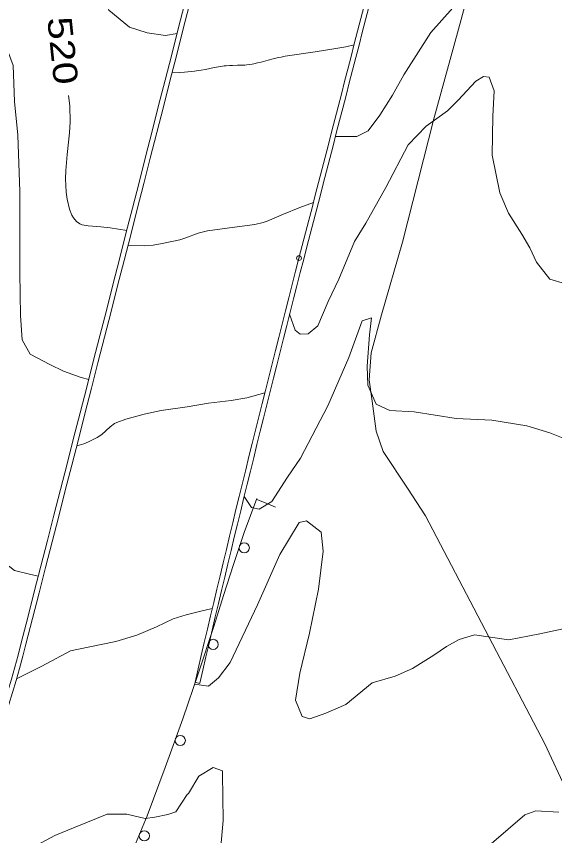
# Model space of a CAD drawing. Extents: x 2361284 to 2366480, y 6976556 to 6985346.
# Drawn here: x 2364928.4 to 2365034.3, y 6979218.9 to 6979380.2 of the extents above; entities that cross this region are included whole.
import ezdxf
from ezdxf.enums import TextEntityAlignment as Align

# ---------------------------------------------------------------- set-up
doc = ezdxf.new("R2010")
doc.units = 0
doc.header["$LTSCALE"] = 1.9
doc.header["$PDMODE"] = 32
doc.header["$PDSIZE"] = 0.95
for name, color, linetype, lineweight in [('12', 7, 'Continuous', 13), ('13', 7, 'Continuous', 13), ('17', 7, 'Continuous', 13), ('3', 7, 'Continuous', 13), ('5', 7, 'Continuous', 13)]:
    doc.layers.add(name, color=color, linetype=linetype, lineweight=lineweight)

msp = doc.modelspace()

# ---------------------------------------------------------------- linework, layer by layer
at = {"layer": '12'}
for points in [[(2365090.866, 6979426.919), (2365090.797, 6979426.888), (2365083.489, 6979425.51), (2365077.442, 6979424.101), (2365067.089, 6979423.363), (2365058.669, 6979422.293), (2365053.493, 6979419.673), (2365048.99, 6979416.8), (2365044.078, 6979409.723), (2365038.145, 6979403.617), (2365033.068, 6979398.048), (2365027.257, 6979391.763), (2365022.139, 6979387.334), (2365014.301, 6979381.889), (2365009.957, 6979377.046), (2365004.624, 6979368.746), (2365002.393, 6979364.705), (2364999.96, 6979360.762), (2364997.599, 6979357.698), (2364995.39, 6979356.567), (2364991.199, 6979356.597)], [(2364994.848, 6979374.593), (2364993.247, 6979374.248), (2364992.444, 6979374.089), (2364991.235, 6979373.878), (2364987.222, 6979373.26), (2364981.299, 6979372.364), (2364980.511, 6979372.226), (2364979.988, 6979372.116), (2364978.949, 6979371.868), (2364977.914, 6979371.596), (2364976.535, 6979371.232), (2364975.843, 6979371.062), (2364975.148, 6979370.908), (2364974.8, 6979370.839), (2364974.274, 6979370.747), (2364973.727, 6979370.675), (2364973.36, 6979370.643), (2364972.623, 6979370.604), (2364971.885, 6979370.588), (2364970.899, 6979370.571), (2364970.407, 6979370.553), (2364969.672, 6979370.502), (2364969.307, 6979370.46), (2364968.652, 6979370.365), (2364967.347, 6979370.135), (2364965.609, 6979369.798), (2364964.739, 6979369.64), (2364963.864, 6979369.503), (2364963.425, 6979369.445), (2364962.121, 6979369.302), (2364961.469, 6979369.242), (2364960.49, 6979369.168), (2364959.019, 6979369.093)], [(2364950.114, 6979338.077), (2364946.849, 6979338.586), (2364945.006, 6979338.78), (2364942.54, 6979338.992), (2364941.311, 6979339.203), (2364940.899, 6979339.34), (2364940.183, 6979339.829), (2364939.605, 6979340.531), (2364939.292, 6979341.075), (2364938.833, 6979342.229), (2364938.349, 6979344.235), (2364938.159, 6979345.573), (2364938.035, 6979348.261), (2364938.087, 6979349.856), (2364938.362, 6979353.047), (2364938.809, 6979357.303), (2364938.941, 6979359.428), (2364938.869, 6979362.611), (2364938.61, 6979364.638)]]:
    msp.add_lwpolyline(points, dxfattribs=at)
at = {"layer": '13'}
for points in [[(2364960.006, 6979376.831), (2364957.759, 6979376.44), (2364954.094, 6979376.955), (2364950.663, 6979378.123), (2364946.581, 6979381.425), (2364944.782, 6979386.648), (2364943.416, 6979393.555), (2364943.388, 6979402.775), (2364943.212, 6979412.914), (2364941.511, 6979427.649), (2364940.075, 6979435.606), (2364938.222, 6979442.218)], [(2364942.612, 6979308.713), (2364941.157, 6979309.129), (2364937.626, 6979310.326), (2364934.944, 6979311.66), (2364931.085, 6979313.663), (2364929.537, 6979316.549), (2364929.192, 6979321.316), (2364929.032, 6979329.745), (2364929.06, 6979345.726), (2364928.664, 6979356.813), (2364927.981, 6979363.437), (2364927.734, 6979370.534), (2364925.659, 6979376.285)], [(2365036.459, 6979327.536), (2365033.369, 6979328.497), (2365030.748, 6979331.812), (2365029.48, 6979334.65), (2365027.914, 6979337.356), (2365025.285, 6979341.452), (2365023.546, 6979345.484), (2365022.016, 6979352.91), (2365022.193, 6979360.543), (2365022.466, 6979365.556), (2365021.47, 6979368.236), (2365020.319, 6979368.376), (2365018.858, 6979367.442), (2365015.353, 6979363.758), (2365013.274, 6979361.628), (2365009.062, 6979358.597), (2365005.476, 6979354.903), (2365001.086, 6979346.491), (2364997.182, 6979339.514), (2364994.957, 6979335.862), (2364991.867, 6979328.472), (2364989.75, 6979324.072), (2364987.745, 6979319.263), (2364985.839, 6979317.704), (2364984.259, 6979317.639), (2364983.232, 6979318.44), (2364982.172, 6979321.59)], [(2364986.854, 6979343.595), (2364984.182, 6979342.58), (2364980.965, 6979341.25), (2364977.747, 6979339.909), (2364976.959, 6979339.627), (2364975.338, 6979339.223), (2364970.33, 6979338.559), (2364965.975, 6979338.017), (2364964.145, 6979337.505), (2364961.758, 6979336.612), (2364960.542, 6979336.235), (2364957.063, 6979335.465), (2364955.301, 6979335.195), (2364953.65, 6979335.05), (2364950.342, 6979335.088)], [(2364932.7, 6979269.966), (2364931.207, 6979270.273), (2364928.04, 6979271.073), (2364925.873, 6979272.802), (2364923.922, 6979274.974), (2364922.403, 6979279.12), (2364921.103, 6979286.476), (2364920.232, 6979293.89), (2364918.914, 6979300.927), (2364918.247, 6979310.091), (2364918.327, 6979323.763), (2364918.245, 6979337.664)], [(2365040.625, 6979295.324), (2365033.427, 6979298.206), (2365028.893, 6979299.573), (2365021.962, 6979300.697), (2365014.95, 6979301.01), (2365006.696, 6979302.322), (2365001.903, 6979302.606), (2364999.231, 6979303.871), (2364997.546, 6979307.595), (2364997.43, 6979311.344), (2364997.862, 6979317.479), (2364998.299, 6979320.873), (2364996.465, 6979320.246), (2364993.843, 6979313.07), (2364989.695, 6979303.54), (2364984.282, 6979293.228), (2364981.767, 6979289.453), (2364978.683, 6979284.655), (2364976.177, 6979283.171), (2364974.644, 6979283.506), (2364973.233, 6979285.682)], [(2364977.269, 6979306.072), (2364973.758, 6979305.119), (2364970.673, 6979304.58), (2364966.168, 6979304.047), (2364961.975, 6979303.307), (2364956.911, 6979302.609), (2364953.548, 6979301.867), (2364949.941, 6979300.878), (2364948.173, 6979300.255), (2364947.684, 6979300.023), (2364946.808, 6979299.395), (2364945.191, 6979297.893), (2364944.291, 6979297.258), (2364942.55, 6979296.409), (2364941.652, 6979296.067), (2364940.265, 6979295.67)], [(2365038.749, 6979260.174), (2365031.404, 6979258.584), (2365025.324, 6979257.407), (2365018.545, 6979258.442), (2365015.523, 6979257.524), (2365013.077, 6979256.091), (2365010.583, 6979254.387), (2365006.347, 6979251.766), (2365002.971, 6979250.264), (2364998.403, 6979248.941), (2364993.264, 6979244.671), (2364989.271, 6979242.953), (2364986.173, 6979241.866), (2364984.666, 6979242.299), (2364983.295, 6979245.526), (2364984.174, 6979250.866), (2364986.07, 6979258.733), (2364987.878, 6979267.42), (2364988.787, 6979274.877), (2364988.352, 6979278.607), (2364985.485, 6979280.875), (2364984.062, 6979280.516), (2364980.232, 6979274.269), (2364975.846, 6979264.336), (2364970.474, 6979252.955), (2364968.192, 6979249.944), (2364966.228, 6979248.295), (2364963.414, 6979248.698)], [(2364966.943, 6979263.591), (2364964.438, 6979262.987), (2364961.804, 6979262.372), (2364959.271, 6979261.598), (2364955.966, 6979259.997), (2364952.121, 6979258.38), (2364947.943, 6979257.121), (2364942.484, 6979255.969), (2364939.059, 6979255.277), (2364933.399, 6979252.263), (2364928.422, 6979249.745)], [(2364967.832, 6979207.917), (2364969.08, 6979221.84), (2364968.982, 6979231.049), (2364968.937, 6979231.609), (2364967.091, 6979232.251), (2364964.326, 6979230.595), (2364962.278, 6979227.186), (2364962, 6979226.984), (2364959.743, 6979223.561), (2364958.178, 6979222.996), (2364955.623, 6979222.512), (2364953.715, 6979222.224), (2364950.117, 6979223.079), (2364946.266, 6979223.113), (2364939.96, 6979220.503), (2364935.936, 6979218.914), (2364931.688, 6979216.584)], [(2365035.198, 6979223.498), (2365030.615, 6979223.724), (2365028.472, 6979222.954), (2365019.089, 6979214.895)]]:
    msp.add_lwpolyline(points, dxfattribs=at)
at = {"layer": '17'}
msp.add_lwpolyline([(2364975.707, 6979285.287), (2364974.439, 6979281.924), (2364973.221, 6979278.553), (2364972.14, 6979275.412), (2364971.09, 6979272.252), (2364969.168, 6979266.143), (2364967.236, 6979260.044), (2364964.213, 6979250.956), (2364961.119, 6979241.895), (2364957.7, 6979232.292), (2364954.1, 6979222.757), (2364951.52, 6979216.473), (2364948.678, 6979210.305), (2364944.409, 6979201.833), (2364939.877, 6979193.501), (2364934.959, 6979184.924), (2364929.839, 6979176.464)], dxfattribs=at)
for centre in [(2364973.247, 6979275.559), (2364967.123, 6979256.531), (2364960.644, 6979237.587), (2364953.568, 6979218.833)]:
    msp.add_circle(centre, 1, dxfattribs=at)
at = {"layer": '3'}
for p, q in [((2364984.936, 6979332.377), (2364984.937, 6979332.378)), ((2364929.326, 6979256.816), (2364929.327, 6979256.819)), ((2364930.257, 6979256.583), (2364930.257, 6979256.581)), ((2364964.473, 6979248.858), (2364963.54, 6979249.079))]:
    msp.add_line(p, q, dxfattribs=at)
msp.add_lwpolyline([(2365050.009, 6979199.098), (2365032.43, 6979236.923), (2365008.922, 6979281.862), (2365005.349, 6979287.301), (2365000.59, 6979294.527), (2364999.182, 6979298.53), (2364998.395, 6979304.453), (2364997.796, 6979308.648), (2364998.235, 6979313.971), (2365000.264, 6979321.472), (2365004.358, 6979335.761), (2365010.528, 6979360.042), (2365015.963, 6979379.624), (2365023.85, 6979409.241), (2365027.391, 6979422.905)], dxfattribs=at)
for centre, radius, start, end in [((2254491.927, 7007547.162), 114003.346, 345.63172, 345.79902), ((2254491.927, 7007547.162), 114004.305, 345.63172, 345.79902), ((2347412.153, 6983892.202), 18153.784, 345.45358, 345.97153), ((2347412.154, 6983892.202), 18154.743, 345.45358, 345.97153), ((2368390.102, 6978453.859), 3517.626, 165.53339, 166.93437), ((2368390.102, 6978453.859), 3516.667, 165.53339, 166.93437), ((2364724.701, 6979308.181), 210.974, 324.53485, 345.90885), ((2364724.701, 6979308.181), 211.934, 324.53485, 345.90885)]:
    msp.add_arc(centre, radius, start, end, dxfattribs=at)
msp.add_point((2364984.007, 6979332.618), dxfattribs=at)
at = {"layer": '5'}
msp.add_lwpolyline([(2364975.707, 6979285.088), (2364977.55, 6979284.338), (2364979.403, 6979283.585)], dxfattribs=at)

# ---------------------------------------------------------------- texts
at = {"layer": '12', "width": 1.25}
msp.add_text(' 520 ', height=4.799, rotation=275.995, dxfattribs=at).set_placement((2364935.133, 6979373.238), align=Align.CENTER)

doc.saveas('drawing.dxf')
